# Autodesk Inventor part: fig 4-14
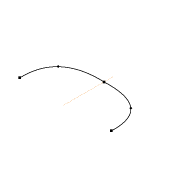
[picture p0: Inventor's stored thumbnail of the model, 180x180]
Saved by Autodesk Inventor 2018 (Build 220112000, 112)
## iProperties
Created: 2012-07
Part Number: fig 4-14
Material: Generic
Document SubType Name: Modeling
Designer: CADCIM
Density: 1 g/cm^3
Appearance: Default
Author: CADCIM
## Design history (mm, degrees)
sketch "Sketch1"
  geometry: L1 (-0.121, 16.232)-(-0.121, 0.498); 5 further points
  constraints: 2 end point, 2 symmetric about line, 1 vertical, 7 other
